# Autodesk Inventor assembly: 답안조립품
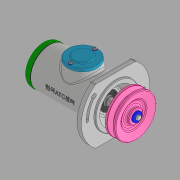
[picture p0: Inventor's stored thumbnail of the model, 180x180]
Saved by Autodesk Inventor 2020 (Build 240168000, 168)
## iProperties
Created: 2022-05
Part Number: 답안조립품
Document SubType Name: Assembly
Designer: User
Author: User
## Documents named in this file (22)
- C:\Users\User\Desktop\720506V1029\답안조립품.iam
- C:\Users\User\Desktop\720506V1029\본체.ipt
- C:\Users\User\Desktop\720506V1029\V-벨트풀리.ipt
- C:\Users\User\Desktop\720506V1029\개스킷.ipt
- C:\Users\User\Desktop\720506V1029\너트 M10.ipt
- C:\Users\User\Desktop\720506V1029\멈춤나사 M3.ipt
- C:\Users\User\Desktop\720506V1029\멈춤링 15 x 1.ipt
- C:\Users\User\Desktop\720506V1029\멈춤링 35 x 1.6.ipt
- C:\Users\User\Desktop\720506V1029\베어링 6202.ipt
- C:\Users\User\Desktop\720506V1029\볼트 M4 x 10.ipt
- C:\Users\User\Desktop\720506V1029\부시1.ipt
- C:\Users\User\Desktop\720506V1029\부시2.ipt
- C:\Users\User\Desktop\720506V1029\사이드 커버.ipt
- 사이드 커버.ipt
- C:\Users\User\Desktop\720506V1029\십자볼트 M3 x 10.ipt
- C:\Users\User\Desktop\720506V1029\오일 실 15 x 30 x 7.ipt
- C:\Users\User\Desktop\720506V1029\와셔 3 x 6.ipt
- C:\Users\User\Desktop\720506V1029\와셔 4 x 16.ipt
- C:\Users\User\Desktop\720506V1029\와셔 10 x 21.ipt
- C:\Users\User\Desktop\720506V1029\축.ipt
- C:\Users\User\Desktop\720506V1029\키 4 x 4.ipt
- C:\Users\User\Desktop\720506V1029\탑 커버.ipt
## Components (3 placed, 3 different names)
1. V-벨트풀리:1
2. 개스킷:1
3. ISO 4017 M4 x 10:1 — 각도:4
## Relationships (1: Angle 1)
- 각도:4 [Angle]: ISO 4017 M4 x 10:1
